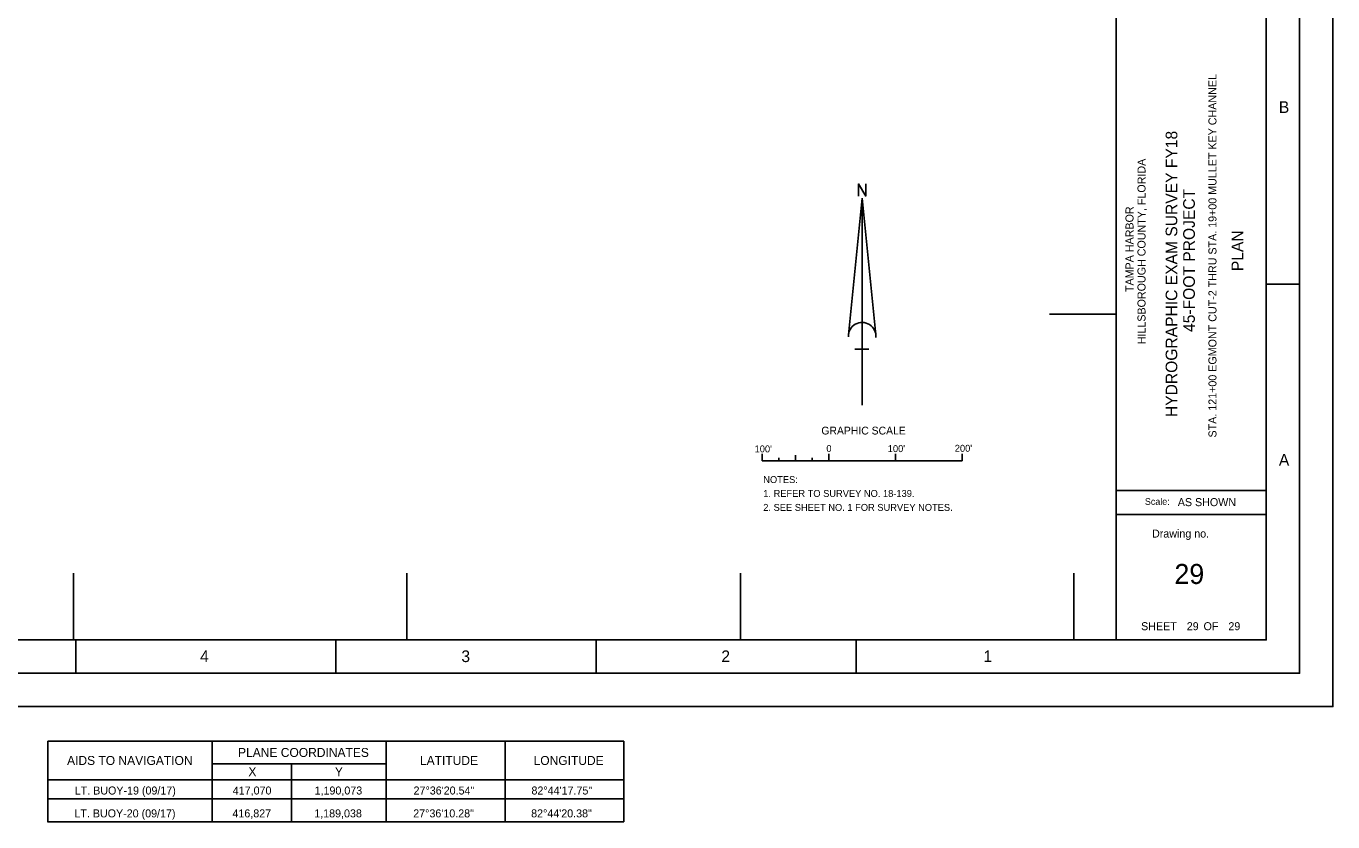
# Model space of a CAD drawing. Extents: x 415488 to 419888, y 1187739 to 1191312.
# Drawn here: x 417929 to 419888, y 1187739 to 1188932 of the extents above; entities that cross this region are included whole.
import ezdxf

# ---------------------------------------------------------------- set-up
doc = ezdxf.new("R2010")
doc.units = 0
for name, color, linetype in [('G-ANNO-NPLT', 7, 'Continuous'), ('G-ANNO-TEXT-DRWG', 7, 'Continuous'), ('G-ANNO-TEXT-PROJ', 7, 'Continuous'), ('G-ANNO-TEXT-TTLB', 7, 'Continuous'), ('G-ANNO-TTLB', 7, 'Continuous'), ('V-ANNO-NOTE', 7, 'Continuous'), ('V-ANNO-SCHD', 7, 'Continuous'), ('V-ANNO-SYMB', 7, 'Continuous'), ('V-TOPO-COOR-STAT', 7, 'Continuous')]:
    doc.layers.add(name, color=color, linetype=linetype)

msp = doc.modelspace()

# ---------------------------------------------------------------- linework, layer by layer
at = {"layer": 'G-ANNO-NPLT'}
msp.add_lwpolyline([(415488.5, 1191311.7), (419888.5, 1191311.7), (419888.5, 1187911.7), (415488.5, 1187911.7)], close=True, dxfattribs=at)
msp.add_lwpolyline([(419888.5, 1187961.7), (419888.5, 1187911.7), (419838.5, 1187911.7)], dxfattribs=at)
at = {"layer": 'G-ANNO-TTLB'}
for p, q in [((419563.4, 1191211.7), (419563.4, 1188011.7)), ((419838.5, 1188545), (419788.5, 1188545)), ((419563.4, 1188235.5), (419788.5, 1188235.5)), ((419563.4, 1188199.8), (419788.5, 1188199.8)), ((418003.5, 1187961.7), (418003.5, 1188011.7)), ((418393.5, 1187961.7), (418393.5, 1188011.7)), ((418783.5, 1187961.7), (418783.5, 1188011.7)), ((419173.5, 1187961.7), (419173.5, 1188011.7))]:
    msp.add_line(p, q, dxfattribs=at)
for points in [[(415538.5, 1187961.7), (419838.5, 1187961.7), (419838.5, 1191261.7), (415538.5, 1191261.7)], [(419788.5, 1191211.7), (415663.5, 1191211.7), (415663.5, 1188011.7), (419788.5, 1188011.7)]]:
    msp.add_lwpolyline(points, close=True, dxfattribs=at)
at = {"layer": 'V-ANNO-NOTE'}
for p, q in [((419032.6, 1188280.1), (419032.6, 1188290.5)), ((419082.6, 1188280.1), (419082.6, 1188288.6)), ((419132.6, 1188280.1), (419132.6, 1188290.5)), ((419132.6, 1188280.1), (419132.6, 1188290.5)), ((419232.6, 1188280.1), (419232.6, 1188290.5)), ((419332.6, 1188280.1), (419332.6, 1188290.5)), ((419032.6, 1188280.1), (419332.6, 1188280.1)), ((419057.6, 1188280.1), (419057.6, 1188284.8)), ((419107.6, 1188280.1), (419107.6, 1188284.8)), ((419132.6, 1188280.1), (419132.6, 1188285.1))]:
    msp.add_line(p, q, dxfattribs=at)
at = {"layer": 'V-ANNO-SCHD'}
for p, q in [((417961.4, 1187859.8), (418825.4, 1187859.8)), ((417961.4, 1187859.8), (417961.4, 1187738.9)), ((418208, 1187859.8), (418208, 1187738.9)), ((418468.8, 1187859.8), (418468.8, 1187738.9)), ((418647.1, 1187859.8), (418647.1, 1187738.9)), ((418825.4, 1187738.9), (418825.4, 1187859.8)), ((418208, 1187826.1), (418468.8, 1187826.1)), ((418326.9, 1187826.1), (418326.9, 1187738.9)), ((417961.4, 1187802), (418825.4, 1187802)), ((417961.4, 1187773.2), (418825.4, 1187773.2)), ((417960.9, 1187738.9), (418825, 1187738.9))]:
    msp.add_line(p, q, dxfattribs=at)
at = {"layer": 'V-ANNO-SYMB'}
for p, q in [((419162, 1188469), (419182.6, 1188673.8)), ((419182.6, 1188363.5), (419182.6, 1188673.8)), ((419203.2, 1188469), (419182.6, 1188673.8)), ((419192.4, 1188447.3), (419171.7, 1188447.3))]:
    msp.add_line(p, q, dxfattribs=at)
msp.add_lwpolyline([(419176.9, 1188677.1), (419176.9, 1188695.2), (419188.1, 1188677.1), (419188.1, 1188695.2)], dxfattribs=at)
msp.add_arc((419182.6, 1188466.9), 20.7, 355.2984, 182.0673, dxfattribs=at)
at = {"layer": 'V-TOPO-COOR-STAT'}
for p, q in [((419463.4, 1188500), (419563.4, 1188500)), ((418000, 1188011.7), (418000, 1188111.7)), ((418500, 1188011.7), (418500, 1188111.7)), ((419000, 1188011.7), (419000, 1188111.7)), ((419500, 1188011.7), (419500, 1188111.7))]:
    msp.add_line(p, q, dxfattribs=at)

# ---------------------------------------------------------------- texts
at = {"layer": 'G-ANNO-TEXT-DRWG'}
for s, height, p in [('STA. 121+00 EGMONT CUT-2 THRU STA. 19+00 MULLET KEY CHANNEL', 12, (419713.9, 1188315.1)), ('PLAN', 17.5, (419754, 1188564.5))]:
    msp.add_text(s, height=height, rotation=90, dxfattribs=at).set_placement(p)
for s, height, p in [('29', 30, (419650.9, 1188095.5)), (' 29          29', 12, (419664.9, 1188026.2))]:
    msp.add_text(s, height=height, dxfattribs=at).set_placement(p)
at = {"layer": 'G-ANNO-TEXT-PROJ'}
for s, height, p in [('HYDROGRAPHIC EXAM SURVEY FY18', 17.5, (419655.2, 1188345.7)), ('HILLSBOROUGH COUNTY, FLORIDA', 12, (419607.5, 1188454.8)), ('45-FOOT PROJECT', 17.5, (419681.5, 1188473.3)), ('TAMPA HARBOR', 12, (419589.5, 1188533.2))]:
    msp.add_text(s, height=height, rotation=90, dxfattribs=at).set_placement(p)
at = {"layer": 'G-ANNO-TEXT-TTLB'}
for s, height, p in [('Scale:', 10, (419606.6, 1188214.1)), ('AS SHOWN', 12, (419655.9, 1188212.2)), ('Drawing no.', 12, (419617.3, 1188165.1)), ('SHEET         OF', 12, (419600.9, 1188026.2))]:
    msp.add_text(s, height=height, dxfattribs=at).set_placement(p)
at = {"layer": 'G-ANNO-TTLB'}
for s, p in [('B', (419807.5, 1188801.7)), ('A', (419807.5, 1188272.9)), ('4', (418189.8, 1187978.4)), ('3', (418581.6, 1187978.4)), ('2', (418971.4, 1187978.4)), ('1', (419364.5, 1187978.4))]:
    msp.add_text(s, height=17.5, dxfattribs=at).set_placement(p)
at = {"layer": 'V-ANNO-NOTE'}
for s, height, p in [('GRAPHIC SCALE', 11.666, (419121.4, 1188319.6)), ("100'", 10.42, (419021.3, 1188292.8)), ('0', 10.4, (419128.9, 1188293.5)), ("100'", 10.42, (419221, 1188293.2)), ("200'", 10.42, (419321.5, 1188293.7)), ('NOTES:', 10.42, (419034.3, 1188246.8)), ('1. REFER TO SURVEY NO. 18-139.', 10.416, (419034.3, 1188226)), ('2. SEE SHEET NO. 1 FOR SURVEY NOTES.', 10.416, (419034.3, 1188205.1))]:
    msp.add_text(s, height=height, dxfattribs=at).set_placement(p)
at = {"layer": 'V-ANNO-SCHD'}
for s, height, p in [('AIDS TO NAVIGATION', 13.471, (417990.3, 1187824.2)), ('PLANE COORDINATES', 13.471, (418246.7, 1187836.2)), ('LONGITUDE', 13.47, (418689.9, 1187824.2)), ('X', 13.5, (418262.2, 1187807.3)), ('Y', 13.5, (418391.9, 1187807.3)), ('LATITUDE', 13.47, (418519.5, 1187824.2))]:
    msp.add_text(s, height=height, rotation=0.0001, dxfattribs=at).set_placement(p)
at = {"layer": 'V-ANNO-SYMB'}
for s, p in [('LT. BUOY-19 (09/17)', (418001.8, 1187779.9)), ('417,070', (418238.8, 1187779.9)), ('1,190,073', (418361.5, 1187779.9)), ('27%%D36\'20.54"', (418509.9, 1187779.9)), ('82%%D44\'17.75"', (418686.7, 1187779.9)), ('LT. BUOY-20 (09/17)', (418001.3, 1187745.6)), ('416,827', (418238.3, 1187745.6)), ('1,189,038', (418361, 1187745.6)), ('27%%D36\'10.28"', (418509.4, 1187745.6)), ('82%%D44\'20.38"', (418686.2, 1187745.6))]:
    msp.add_text(s, height=12, dxfattribs=at).set_placement(p)

doc.saveas('drawing.dxf')
